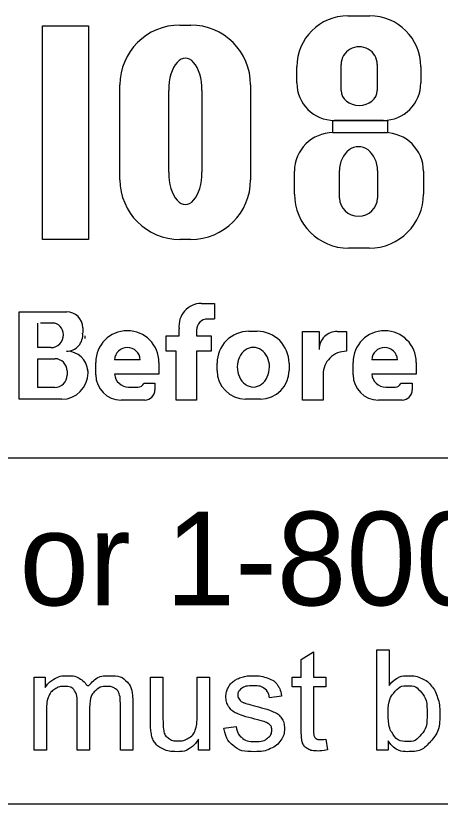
# Model space of a CAD drawing. Extents: x 0 to 45.5, y 0 to 22.
# Drawn here: x 4.796 to 5.431, y 2.596 to 3.776 of the extents above; entities that cross this region are included whole.
import ezdxf

# ---------------------------------------------------------------- set-up
doc = ezdxf.new("R2010")
doc.units = 0
doc.layers.add('SH_Data', color=7, linetype='Continuous')
doc.layers.add('SH_Text', color=7, linetype='Continuous')

msp = doc.modelspace()

# ---------------------------------------------------------------- linework, layer by layer
at = {"layer": 'SH_Data'}
for p, q in [((7.2275, 3.1136), (2.9775, 3.1136)), ((7.2275, 2.5957), (2.9775, 2.5957))]:
    msp.add_line(p, q, dxfattribs=at)
at = {"layer": 'SH_Text'}
for p, q in [((5.2931, 3.776), (5.3258, 3.776)), ((5.0416, 3.762), (5.0581, 3.762)), ((5.2168, 3.6754), (5.2168, 3.6997)), ((5.283, 3.664), (5.283, 3.7033)), ((5.3371, 3.7033), (5.3371, 3.664)), ((5.4022, 3.6997), (5.4022, 3.6754)), ((4.9521, 3.5306), (4.9521, 3.6726)), ((5.1476, 3.6726), (5.1476, 3.5306)), ((5.025, 3.5419), (5.025, 3.6643)), ((5.0748, 3.6643), (5.0748, 3.5419)), ((5.3462, 3.6194), (5.2728, 3.6194)), ((5.271, 3.6011), (5.3483, 3.6011)), ((5.2131, 3.5092), (5.2131, 3.5432)), ((5.2806, 3.5032), (5.2806, 3.5442)), ((5.3374, 3.5442), (5.3374, 3.5032)), ((5.4062, 3.5432), (5.4062, 3.5092)), ((5.0581, 3.4411), (5.0416, 3.4411)), ((5.3252, 3.4283), (5.2941, 3.4283)), ((5.0739, 3.3455), (5.0934, 3.3455)), ((5.0934, 3.3455), (5.0934, 3.3225)), ((4.8013, 3.202), (4.8013, 3.3327)), ((4.8013, 3.3327), (4.8725, 3.3327)), ((5.0934, 3.322), (5.0832, 3.322)), ((4.8293, 3.2792), (4.8293, 3.3161)), ((4.8545, 3.3161), (4.8332, 3.3161)), ((4.8963, 3.3089), (4.8963, 3.301)), ((5.0406, 3.2971), (5.0406, 3.3076)), ((5.0667, 3.3055), (5.0667, 3.2971)), ((5.0213, 3.2741), (5.0213, 3.2971)), ((5.0213, 3.2971), (5.0406, 3.2971)), ((5.0667, 3.2971), (5.0883, 3.2971)), ((5.0883, 3.2971), (5.0883, 3.2741)), ((5.1451, 3.3037), (5.1573, 3.3037)), ((5.2254, 3.2008), (5.2254, 3.3035)), ((5.2254, 3.3035), (5.2499, 3.3035)), ((5.2499, 3.3035), (5.2499, 3.2766)), ((5.2772, 3.3035), (5.291, 3.3035)), ((5.291, 3.3035), (5.291, 3.2738)), ((4.8487, 3.2792), (4.8293, 3.2792)), ((5.0362, 3.2741), (5.0213, 3.2741)), ((5.0362, 3.2008), (5.0362, 3.2741)), ((5.0883, 3.2741), (5.0667, 3.2741)), ((5.0667, 3.2741), (5.0667, 3.2008)), ((4.8293, 3.2198), (4.8293, 3.2627)), ((4.8293, 3.2627), (4.8548, 3.2627)), ((4.9824, 3.2611), (4.9439, 3.2611)), ((5.3674, 3.2611), (5.3288, 3.2611)), ((4.9159, 3.2387), (4.9159, 3.2572)), ((5.0104, 3.2572), (5.0104, 3.2395)), ((5.0973, 3.2451), (5.0973, 3.2559)), ((5.2051, 3.2559), (5.2051, 3.2451)), ((5.3008, 3.2387), (5.3008, 3.2572)), ((5.3953, 3.2572), (5.3953, 3.2395)), ((4.8729, 3.2445), (4.8729, 3.2382)), ((4.9043, 3.2416), (4.9043, 3.2413)), ((5.0104, 3.2395), (4.944, 3.2395)), ((5.2559, 3.2389), (5.2559, 3.2008)), ((5.3953, 3.2395), (5.3289, 3.2395)), ((4.9876, 3.2258), (5.0045, 3.2258)), ((5.0045, 3.2258), (5.0045, 3.216)), ((5.3725, 3.2258), (5.3894, 3.2258)), ((5.3894, 3.2258), (5.3894, 3.216)), ((4.8546, 3.2198), (4.8293, 3.2198)), ((4.9649, 3.2203), (4.979, 3.2203)), ((5.3498, 3.2203), (5.3639, 3.2203)), ((4.865, 3.202), (4.8013, 3.202)), ((4.9892, 3.2008), (4.9538, 3.2008)), ((5.0667, 3.2008), (5.0362, 3.2008)), ((5.1623, 3.2023), (5.1401, 3.2023)), ((5.2559, 3.2008), (5.2254, 3.2008)), ((5.3742, 3.2008), (5.3388, 3.2008))]:
    msp.add_line(p, q, dxfattribs=at)
for points in [[(4.8364, 3.761), (4.9052, 3.761), (4.9052, 3.441), (4.8364, 3.441)], [(5.2706, 3.6195), (5.3523, 3.6195), (5.3523, 3.601), (5.2706, 3.601)]]:
    msp.add_lwpolyline(points, close=True, dxfattribs=at)
for points in [[(5.2233, 2.7087), (5.2233, 2.7714), (5.2097, 2.7714), (5.2097, 2.7857), (5.2233, 2.7857), (5.2233, 2.8126), (5.2417, 2.8237), (5.2417, 2.7857), (5.2601, 2.7857), (5.2601, 2.7714), (5.2417, 2.7714), (5.2417, 2.7076)], [(5.3534, 2.6768), (5.3363, 2.6768), (5.3363, 2.827), (5.3548, 2.827), (5.3548, 2.7735)], [(4.8236, 2.6768), (4.8236, 2.7857), (4.8401, 2.7857), (4.8401, 2.7703)], [(4.9979, 2.7183), (4.9979, 2.7857), (5.0164, 2.7857), (5.0164, 2.7254)], [(5.0676, 2.7274), (5.0676, 2.7857), (5.0861, 2.7857), (5.0861, 2.6768), (5.0696, 2.6768)], [(4.9711, 2.7515), (4.9711, 2.6768), (4.9527, 2.6768), (4.9527, 2.7453)], [(5.194, 2.7575), (5.1759, 2.7551)], [(4.9067, 2.74), (4.9067, 2.6768), (4.8883, 2.6768), (4.8883, 2.7475)], [(4.842, 2.7333), (4.842, 2.6768), (4.8236, 2.6768)], [(5.1076, 2.7094), (5.1258, 2.7122)], [(5.0696, 2.6768), (5.0696, 2.6929)], [(5.2601, 2.6933), (5.2628, 2.677)], [(5.3534, 2.6905), (5.3534, 2.6768)]]:
    msp.add_lwpolyline(points, dxfattribs=at)
for centre, radius, start, end in [((5.2931, 3.6997), 0.0763, 90, 180), ((5.3258, 3.6997), 0.0763, 0, 90), ((5.0416, 3.6726), 0.0895, 90, 180), ((5.0581, 3.6726), 0.0895, 0, 90), ((5.2728, 3.6754), 0.056, 180, 270), ((5.3462, 3.6754), 0.056, 270, 0), ((5.271, 3.5432), 0.0579, 90, 180), ((5.3483, 3.5432), 0.0579, 0, 90), ((5.0416, 3.5306), 0.0895, 180, 270), ((5.0581, 3.5306), 0.0895, 270, 0), ((5.2941, 3.5092), 0.081, 180, 270), ((5.3252, 3.5092), 0.081, 270, 0), ((5.0739, 3.3119), 0.0335, 90, 187.5187), ((4.8725, 3.3089), 0.0238, 0, 90), ((5.0832, 3.3055), 0.0165, 90, 180), ((4.8505, 3.2993), 0.0169, 357.8325, 90), ((4.8487, 3.2979), 0.0187, 270, 2.0582), ((4.8721, 3.2982), 0.0243, 270, 6.6529), ((4.8827, 3.2967), 0.0175, 347.4023, 0), ((4.9631, 3.2572), 0.0473, 0, 180), ((5.1451, 3.2559), 0.0478, 90, 180), ((5.1573, 3.2559), 0.0478, 0, 90), ((5.2768, 3.2766), 0.0269, 89.2449, 180), ((5.3481, 3.2572), 0.0473, 0, 180), ((4.8722, 3.2418), 0.0321, 4.0748, 90), ((4.9632, 3.2601), 0.0193, 2.9632, 177.0368), ((5.2908, 3.2389), 0.0349, 89.6033, 180), ((5.3481, 3.2601), 0.0193, 2.9632, 177.0368), ((4.8548, 3.2445), 0.0181, 0, 90), ((4.8714, 3.2416), 0.033, 0, 11.7502), ((4.8546, 3.2382), 0.0184, 270, 0), ((4.865, 3.2413), 0.0393, 270, 0), ((4.9538, 3.2387), 0.038, 180, 270), ((4.9649, 3.2413), 0.021, 184.827, 270), ((5.1401, 3.2451), 0.0428, 180, 270), ((5.1623, 3.2451), 0.0428, 270, 0), ((5.3388, 3.2387), 0.038, 180, 270), ((5.3498, 3.2413), 0.021, 184.827, 270), ((4.979, 3.2296), 0.00938, 270, 335.9979), ((5.3639, 3.2296), 0.00938, 270, 335.9979), ((4.9892, 3.216), 0.0152, 270, 0), ((5.3742, 3.216), 0.0152, 270, 0)]:
    msp.add_arc(centre, radius, start, end, dxfattribs=at)
for centre, major_axis, ratio, start_param, end_param in [((5.31, 3.7033), (0.0271, 0), 0.969373, 0, 3.141593), ((5.0499, 3.6643), (0, 0.0484), 0.514403, 4.712389, 7.853982), ((5.31, 3.664), (0.0271, 0), 0.818453, 3.141593, 6.283185), ((5.309, 3.5442), (0, 0.0358), 0.794529, 4.712389, 7.853982), ((5.0499, 3.5419), (0, 0.0484), 0.514403, 1.570796, 4.712389), ((5.309, 3.5032), (0.0284, 0), 0.959837, 3.141593, 6.283185), ((5.1517, 3.2505), (0, 0.029), 0.832186, 4.712389, 7.853982), ((5.1517, 3.2505), (0, 0.0302), 0.797287, 1.570796, 4.712389)]:
    msp.add_ellipse(centre, major_axis=major_axis, ratio=ratio, start_param=start_param, end_param=end_param, dxfattribs=at)
for points in [[(4.8401, 2.7703), (4.8452, 2.7783), (4.8537, 2.7832), (4.8622, 2.7881), (4.8731, 2.7881), (4.8852, 2.7881), (4.8929, 2.7831), (4.9007, 2.778), (4.9038, 2.769), (4.9168, 2.7881), (4.9375, 2.7881), (4.9537, 2.7881), (4.9624, 2.7791), (4.9711, 2.7702), (4.9711, 2.7515)], [(5.1258, 2.7122), (5.1273, 2.7012), (5.1343, 2.6954), (5.1414, 2.6896), (5.154, 2.6896), (5.1668, 2.6896), (5.1729, 2.6947), (5.1791, 2.6999), (5.1791, 2.7069), (5.1791, 2.7131), (5.1736, 2.7167), (5.1698, 2.7192), (5.1548, 2.723), (5.1345, 2.7281), (5.1266, 2.7318), (5.1188, 2.7356), (5.1147, 2.7422), (5.1107, 2.7488), (5.1107, 2.7568), (5.1107, 2.764), (5.114, 2.7702), (5.1173, 2.7764), (5.1231, 2.7805), (5.1274, 2.7837), (5.1348, 2.7859), (5.1423, 2.7881), (5.1508, 2.7881), (5.1636, 2.7881), (5.1733, 2.7844), (5.183, 2.7807), (5.1876, 2.7744), (5.1922, 2.7681), (5.194, 2.7575)], [(5.3548, 2.7735), (5.3664, 2.7881), (5.3846, 2.7881), (5.3946, 2.7881), (5.4036, 2.784), (5.4125, 2.78), (5.4183, 2.7727), (5.4241, 2.7654), (5.4274, 2.755), (5.4306, 2.7447), (5.4306, 2.7329), (5.4306, 2.705), (5.4168, 2.6897), (5.403, 2.6744), (5.3836, 2.6744), (5.3644, 2.6744), (5.3534, 2.6905)], [(4.8883, 2.7475), (4.8883, 2.7598), (4.8838, 2.7659), (4.8793, 2.7721), (4.869, 2.7721), (4.8612, 2.7721), (4.8546, 2.768), (4.848, 2.7639), (4.845, 2.756), (4.842, 2.7481), (4.842, 2.7333)], [(4.9527, 2.7453), (4.9527, 2.7564), (4.9509, 2.7613), (4.9491, 2.7661), (4.9444, 2.7691), (4.9397, 2.7721), (4.9333, 2.7721), (4.9219, 2.7721), (4.9143, 2.7644), (4.9067, 2.7568), (4.9067, 2.74)], [(5.1759, 2.7551), (5.1747, 2.7635), (5.1688, 2.7683), (5.1629, 2.773), (5.1521, 2.773), (5.1394, 2.773), (5.1339, 2.7688), (5.1285, 2.7646), (5.1285, 2.7589), (5.1285, 2.7553), (5.1308, 2.7525), (5.133, 2.7495), (5.1378, 2.7475), (5.1406, 2.7465), (5.1542, 2.7428), (5.1737, 2.7376), (5.1815, 2.7343), (5.1893, 2.7309), (5.1937, 2.7246), (5.1981, 2.7183), (5.1981, 2.7088), (5.1981, 2.6996), (5.1927, 2.6915), (5.1873, 2.6834), (5.1772, 2.6789), (5.167, 2.6744), (5.1542, 2.6744), (5.1329, 2.6744), (5.1218, 2.6832), (5.1107, 2.6921), (5.1076, 2.7094)], [(5.3532, 2.7321), (5.3532, 2.7125), (5.3585, 2.7038), (5.3672, 2.6896), (5.382, 2.6896), (5.3941, 2.6896), (5.4029, 2.7001), (5.4116, 2.7106), (5.4116, 2.7314), (5.4116, 2.7527), (5.4032, 2.7628), (5.3948, 2.773), (5.3828, 2.773), (5.3708, 2.773), (5.362, 2.7625), (5.3532, 2.752), (5.3532, 2.7321)], [(5.0164, 2.7254), (5.0164, 2.7109), (5.0175, 2.7059), (5.0192, 2.6986), (5.0249, 2.6945), (5.0305, 2.6904), (5.0388, 2.6904), (5.0471, 2.6904), (5.0543, 2.6946), (5.0616, 2.6989), (5.0646, 2.7062), (5.0676, 2.7135), (5.0676, 2.7274)], [(5.0696, 2.6929), (5.0569, 2.6744), (5.0351, 2.6744), (5.0255, 2.6744), (5.0171, 2.6781), (5.0088, 2.6818), (5.0047, 2.6874), (5.0007, 2.693), (4.9991, 2.7011), (4.9979, 2.7065), (4.9979, 2.7183)], [(5.2628, 2.677), (5.255, 2.6754), (5.2488, 2.6754), (5.2388, 2.6754), (5.2333, 2.6785), (5.2278, 2.6817), (5.2255, 2.6869), (5.2233, 2.6921), (5.2233, 2.7087)], [(5.2417, 2.7076), (5.2417, 2.6997), (5.2427, 2.6975), (5.2436, 2.6952), (5.2458, 2.6939), (5.248, 2.6925), (5.2521, 2.6925), (5.2551, 2.6925), (5.2601, 2.6933)]]:
    msp.add_open_spline(points, degree=3, dxfattribs=at)

# ---------------------------------------------------------------- texts
msp.add_text('OHIO811, 8-1-1, or 1-800-362-2764', height=0.14, dxfattribs=at).set_placement((3.3658, 2.8935))

doc.saveas('drawing.dxf')
